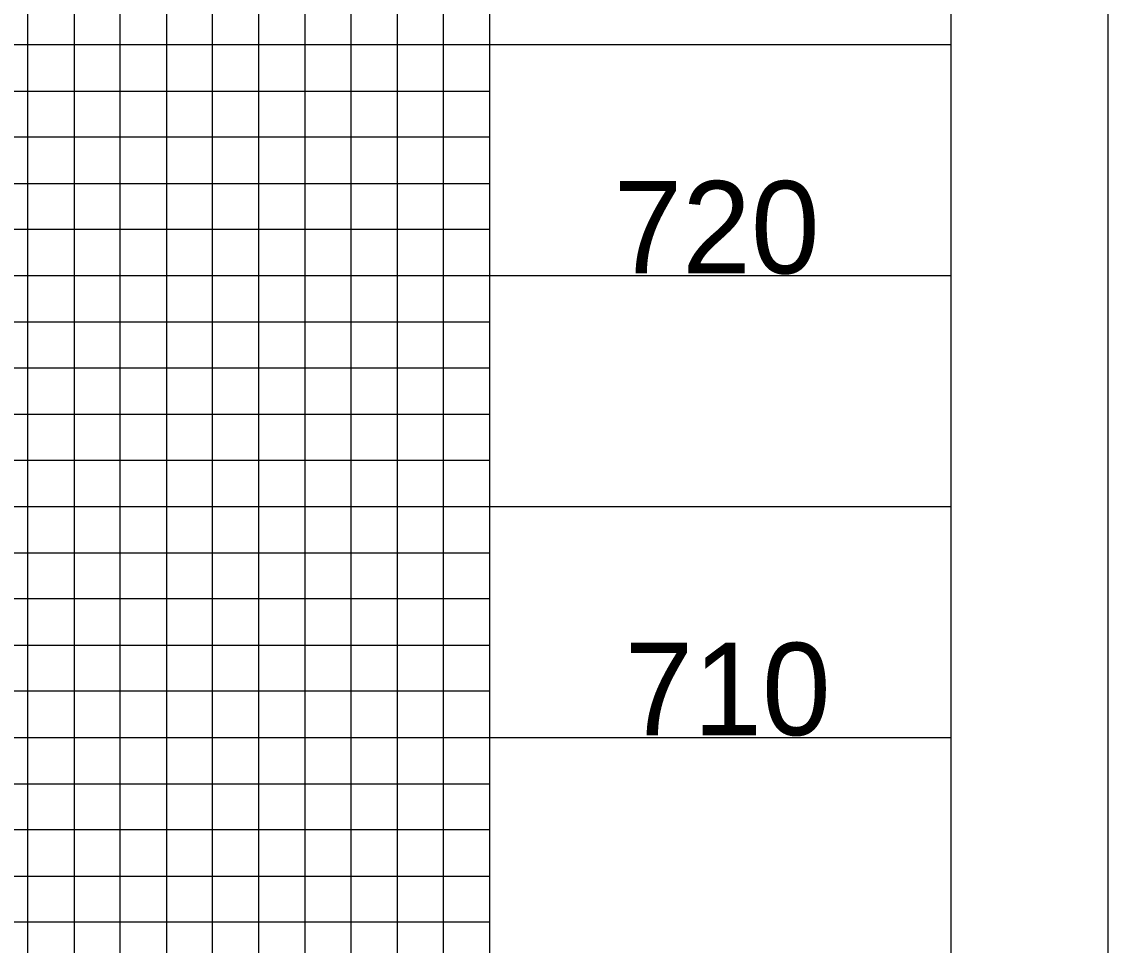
# Model space of a CAD drawing. Extents: x 1524869 to 1526553, y 501099 to 502199.
# Drawn here: x 1526435.4 to 1526553.1, y 501276.1 to 501376.1 of the extents above; entities that cross this region are included whole.
import ezdxf

# ---------------------------------------------------------------- set-up
doc = ezdxf.new("R2010")
doc.units = 0
for name, color, linetype in [('Exist Vertical Profile Vertical Axis Label', 7, 'Continuous'), ('Sheet Layout Profile Border Port 1', 7, 'Continuous'), ('Sheet Plot Border Outside CELL', 7, 'Continuous'), ('Sheet Profile CELL', 7, 'Continuous'), ('Sheet Profile Grid Major CELL', 7, 'Continuous'), ('Sheet Profile Grid Middle CELL', 7, 'Continuous'), ('Sheet Profile Grid Minor CELL', 7, 'Continuous')]:
    doc.layers.add(name, color=color, linetype=linetype)

msp = doc.modelspace()

# ---------------------------------------------------------------- linework, layer by layer
at = {"layer": 'Sheet Layout Profile Border Port 1'}
msp.add_lwpolyline([(1525536.08, 501648.56), (1526486.08, 501648.56), (1526486.08, 501148.56), (1525536.08, 501148.56)], close=True, dxfattribs=at)
at = {"layer": 'Sheet Plot Border Outside CELL'}
msp.add_lwpolyline([(1524869.08, 501098.56), (1526553.08, 501098.56), (1526553.08, 502198.56), (1524869.08, 502198.56)], close=True, dxfattribs=at)
at = {"layer": 'Sheet Profile CELL'}
msp.add_lwpolyline([(1526536.08, 502173.56), (1525036.08, 502173.56), (1525036.08, 501123.56), (1526536.08, 501123.56)], close=True, dxfattribs=at)
at = {"layer": 'Sheet Profile Grid Major CELL'}
for points in [[(1525986.08, 501148.56), (1526036.08, 501148.56), (1526036.08, 501648.56), (1526086.08, 501648.56), (1526086.08, 501148.56), (1526136.08, 501148.56), (1526136.08, 501648.56), (1526186.08, 501648.56), (1526186.08, 501148.56), (1526236.08, 501148.56), (1526236.08, 501648.56), (1526286.08, 501648.56), (1526286.08, 501148.56), (1526336.08, 501148.56), (1526336.08, 501648.56), (1526386.08, 501648.56), (1526386.08, 501148.56), (1526436.08, 501148.56), (1526436.08, 501148.56), (1526436.08, 501648.56), (1526486.08, 501648.56), (1526486.08, 501148.56)], [(1526536.08, 501348.56), (1525036.08, 501348.56), (1525036.08, 501298.56), (1526536.08, 501298.56)]]:
    msp.add_lwpolyline(points, dxfattribs=at)
at = {"layer": 'Sheet Profile Grid Middle CELL'}
for points in [[(1526011.08, 501148.56), (1526061.08, 501148.56), (1526061.08, 501648.56), (1526111.08, 501648.56), (1526111.08, 501148.56), (1526161.08, 501148.56), (1526161.08, 501648.56), (1526211.08, 501648.56), (1526211.08, 501148.56), (1526261.08, 501148.56), (1526261.08, 501648.56), (1526311.08, 501648.56), (1526311.08, 501148.56), (1526361.08, 501148.56), (1526361.08, 501648.56), (1526411.08, 501648.56), (1526411.08, 501148.56), (1526461.08, 501148.56), (1526461.08, 501648.56)], [(1526536.08, 501373.56), (1525036.08, 501373.56), (1525036.08, 501323.56), (1526536.08, 501323.56)]]:
    msp.add_lwpolyline(points, dxfattribs=at)
at = {"layer": 'Sheet Profile Grid Minor CELL'}
for p, q in [((1526036.08, 501368.56), (1526486.08, 501368.56)), ((1526486.08, 501363.56), (1526036.08, 501363.56)), ((1526036.08, 501358.56), (1526486.08, 501358.56)), ((1526486.08, 501353.56), (1526036.08, 501353.56)), ((1526036.08, 501343.56), (1526486.08, 501343.56)), ((1526486.08, 501338.56), (1526036.08, 501338.56)), ((1526036.08, 501333.56), (1526486.08, 501333.56)), ((1526486.08, 501328.56), (1526036.08, 501328.56)), ((1526036.08, 501318.56), (1526486.08, 501318.56)), ((1526486.08, 501313.56), (1526036.08, 501313.56)), ((1526036.08, 501308.56), (1526486.08, 501308.56)), ((1526486.08, 501303.56), (1526036.08, 501303.56)), ((1526036.08, 501293.56), (1526486.08, 501293.56)), ((1526486.08, 501288.56), (1526036.08, 501288.56)), ((1526036.08, 501283.56), (1526486.08, 501283.56)), ((1526486.08, 501278.56), (1526036.08, 501278.56))]:
    msp.add_line(p, q, dxfattribs=at)
for points in [[(1526441.08, 501648.56), (1526441.08, 501148.56), (1526446.08, 501148.56), (1526446.08, 501648.56)], [(1526451.08, 501648.56), (1526451.08, 501148.56), (1526456.08, 501148.56), (1526456.08, 501648.56)], [(1526466.08, 501648.56), (1526466.08, 501148.56), (1526471.08, 501148.56), (1526471.08, 501648.56)], [(1526476.08, 501648.56), (1526476.08, 501148.56), (1526481.08, 501148.56), (1526481.08, 501648.56)]]:
    msp.add_lwpolyline(points, dxfattribs=at)

# ---------------------------------------------------------------- texts
at = {"layer": 'Exist Vertical Profile Vertical Axis Label'}
for s, p in [('720', (1526499.51, 501348.81)), ('710', (1526500.71, 501298.81))]:
    msp.add_text(s, height=10, dxfattribs=at).set_placement(p)

doc.saveas('drawing.dxf')
